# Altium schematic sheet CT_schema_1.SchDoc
size 506 x 258 mm
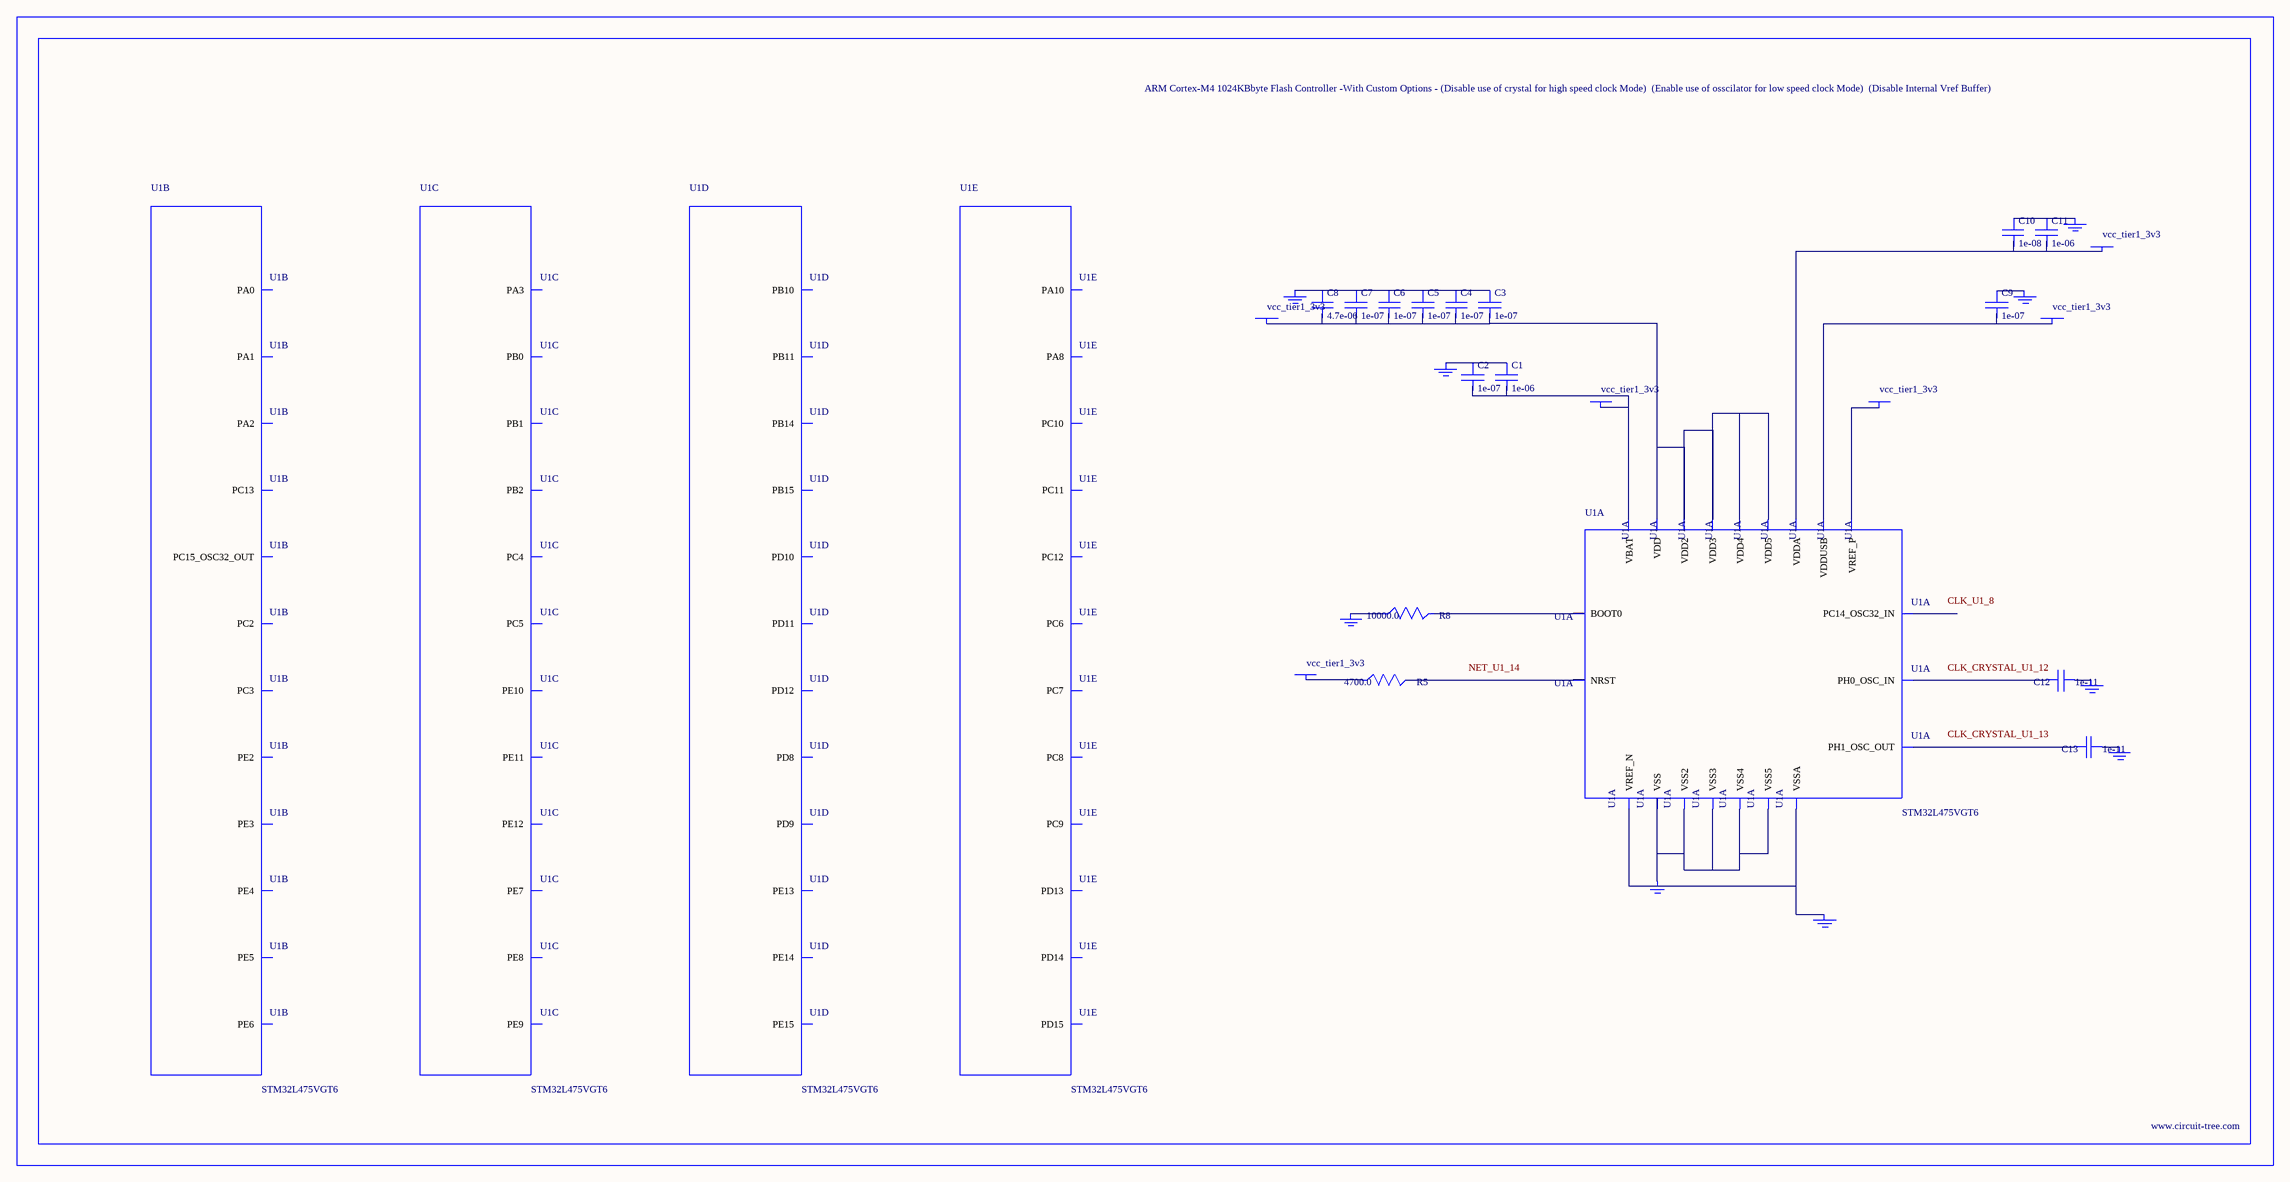
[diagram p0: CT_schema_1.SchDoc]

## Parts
BORDER0  (no value)
C1  1e-06  [C0603]
C2  1e-07  [C0603]
C3  1e-07  [C0603]
C4  1e-07  [C0603]
C5  1e-07  [C0603]
C6  1e-07  [C0603]
C7  1e-07  [C0603]
C8  4.7e-06  [C0603]
C9  1e-07  [C0603]
C10  1e-08  [C0603]
C11  1e-06  [C0603]
C12  1e-11  [C0402]
C13  1e-11  [C0402]
GND_INSTANCE_0_0  (no value)
GND_INSTANCE_0_1  (no value)
GND_INSTANCE_0_2  (no value)
GND_INSTANCE_0_3  (no value)
GND_INSTANCE_0_4  (no value)
GND_INSTANCE_0_5  (no value)
GND_INSTANCE_0_6  (no value)
GND_INSTANCE_0_7  (no value)
GND_INSTANCE_0_8  (no value)
POWER_INSTANCE_0_0  vcc_tier1_3v3
POWER_INSTANCE_0_1  vcc_tier1_3v3
POWER_INSTANCE_0_2  vcc_tier1_3v3
POWER_INSTANCE_0_3  vcc_tier1_3v3
POWER_INSTANCE_0_4  vcc_tier1_3v3
POWER_INSTANCE_0_5  vcc_tier1_3v3
R5  4700.0  [R0603]
R8  10000.0  [R0603]
U1  STM32L475VGT6  [LQFP100]  (parts A,B,C,D,E of 11)

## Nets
NetC1_1: C1.1 C2.1 GND_INSTANCE_0_0.0(GND)
NetC1_2: C1.2 C2.2 POWER_INSTANCE_0_0.0(PWR) U1.6(VBAT)
NetC3_1: C3.1 C4.1 C5.1 C6.1 C7.1 C8.1 GND_INSTANCE_0_1.0(GND)
NetC3_2: C3.2 C4.2 C5.2 C6.2 C7.2 C8.2 POWER_INSTANCE_0_1.0(PWR) U1.11(VDD) U1.28(VDD2) U1.50(VDD3) U1.75(VDD4) U1.100(VDD5)
NetC9_1: C9.1 GND_INSTANCE_0_6.0(GND)
NetC9_2: C9.2 POWER_INSTANCE_0_4.0(PWR) U1.73(VDDUSB)
NetC10_1: C10.1 C11.1 GND_INSTANCE_0_5.0(GND)
NetC10_2: C10.2 C11.2 POWER_INSTANCE_0_3.0(PWR) U1.22(VDDA)
NetC12_1: C12.1 GND_INSTANCE_0_2.0(GND)
NetC12_2: C12.2 U1.12(PH0_OSC_IN)
NetC13_1: C13.1 GND_INSTANCE_0_3.0(GND)
NetC13_2: C13.2 U1.13(PH1_OSC_OUT)
NetGND_INSTANCE_0_4_0: GND_INSTANCE_0_4.0(GND) U1.19(VSSA) U1.20(VREF_N)
NetGND_INSTANCE_0_7_0: GND_INSTANCE_0_7.0(GND) R8.1
NetGND_INSTANCE_0_8_0: GND_INSTANCE_0_8.0(GND) U1.10(VSS) U1.27(VSS2) U1.49(VSS3) U1.74(VSS4) U1.99(VSS5)
NetPOWER_INSTANCE_0_2_0: POWER_INSTANCE_0_2.0(PWR) U1.21(VREF_P)
NetPOWER_INSTANCE_0_5_0: POWER_INSTANCE_0_5.0(PWR) R5.1
NetR5_2: R5.2 U1.14(NRST)
NetR8_2: R8.2 U1.94(BOOT0)

Not connected (* = marked no-connect by the designer): U1 1(PE2) 2(PE3) 3(PE4) 4(PE5) 5(PE6) 7(PC13) 8(PC14_OSC32_IN) 9(PC15_OSC32_OUT) 17(PC2) 18(PC3) 23(PA0) 24(PA1) 25(PA2) 26(PA3) 33(PC4) 34(PC5) 35(PB0) 36(PB1) 37(PB2) 38(PE7) 39(PE8) 40(PE9) 41(PE10) 42(PE11) 43(PE12) 44(PE13) 45(PE14) 46(PE15) 47(PB10) 48(PB11) 53(PB14) 54(PB15) 55(PD8) 56(PD9) 57(PD10) 58(PD11) 59(PD12) 60(PD13) 61(PD14) 62(PD15) 63(PC6) 64(PC7) 65(PC8) 66(PC9) 67(PA8) 69(PA10) 78(PC10) 79(PC11) 80(PC12)

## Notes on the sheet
- Labels drawn without touching a wire or pin: CLK_CRYSTAL_U1_12, CLK_CRYSTAL_U1_13, CLK_U1_8, NET_U1_14

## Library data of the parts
BORDER0 = BORDER_PAGE0
C1 C11 = C0603C105K3RACTU
C2-C7 C9 = 06035C104K4Z2A
C8 = GRM188R6YA475KE15D
C10 = 06035C103K4Z2A
C12 C13 = C0402C100K3GACTU
GND_INSTANCE_0_0-GND_INSTANCE_0_8 = GND
POWER_INSTANCE_0_0-POWER_INSTANCE_0_5 = PWR
R5 = RC0603JR-074K7L
R8 = RC0603JR-0710KL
